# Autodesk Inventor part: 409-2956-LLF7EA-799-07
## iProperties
Created: 2010-11
Part Number: 409-2956-LLF7EA-799-07
Material: 3/4" OD TUBE - SS
Document SubType Name: Modeling
Designer: S. Boerckel
Engineer: Steve Boerckel
Density: 8.08 g/cm^3
Description: DRAIN TUBING
Mass: 332.362 g
Surface Area: 500.097 cm^2
Volume: 41.134 cm^3
User Status: CUT/TUBE BEND
Length: 17.945 in
Author: S. Boerckel
Revision Number: 0
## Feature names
1. TaggingFeature1
